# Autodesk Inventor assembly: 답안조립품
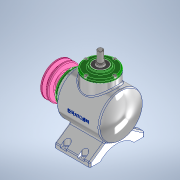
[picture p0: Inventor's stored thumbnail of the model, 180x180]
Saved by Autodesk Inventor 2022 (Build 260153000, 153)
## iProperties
Created: 2023-04
Part Number: 답안조립품
Document SubType Name: Assembly
Designer: Admin
Author: Admin
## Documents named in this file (17)
- C:\Users\Admin\Desktop\730411V1016\답안조립품.iam
- C:\Users\Admin\Desktop\730411V1016\본체.ipt
- C:\Users\Admin\Desktop\730411V1016\커버.ipt
- C:\Users\Admin\Desktop\730411V1016\베어링 6203.ipt
- C:\Users\Admin\Desktop\730411V1016\오일실 17 x 32 x 8.ipt
- C:\Users\Admin\Desktop\730411V1016\메인 축.ipt
- 메인 축.ipt
- C:\Users\Admin\Desktop\730411V1016\키 5 x 5 x 14.ipt
- C:\Users\Admin\Desktop\730411V1016\메인 베벨기어.ipt
- C:\Users\Admin\Desktop\730411V1016\서브 축.ipt
- 서브 축.ipt
- C:\Users\Admin\Desktop\730411V1016\키 4 x 4 x 14.ipt
- C:\Users\Admin\Desktop\730411V1016\서브 베벨기어.ipt
- C:\Users\Admin\Desktop\730411V1016\V-벨트풀리.ipt
- C:\Users\Admin\Desktop\730411V1016\볼트 M4 x 10.ipt
- C:\Users\Admin\Desktop\730411V1016\와셔 4 x 16.ipt
- C:\Users\Admin\Desktop\730411V1016\육각볼트 M4 x 8.ipt
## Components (1 placed, 1 different names)
1. V-벨트풀리:1
